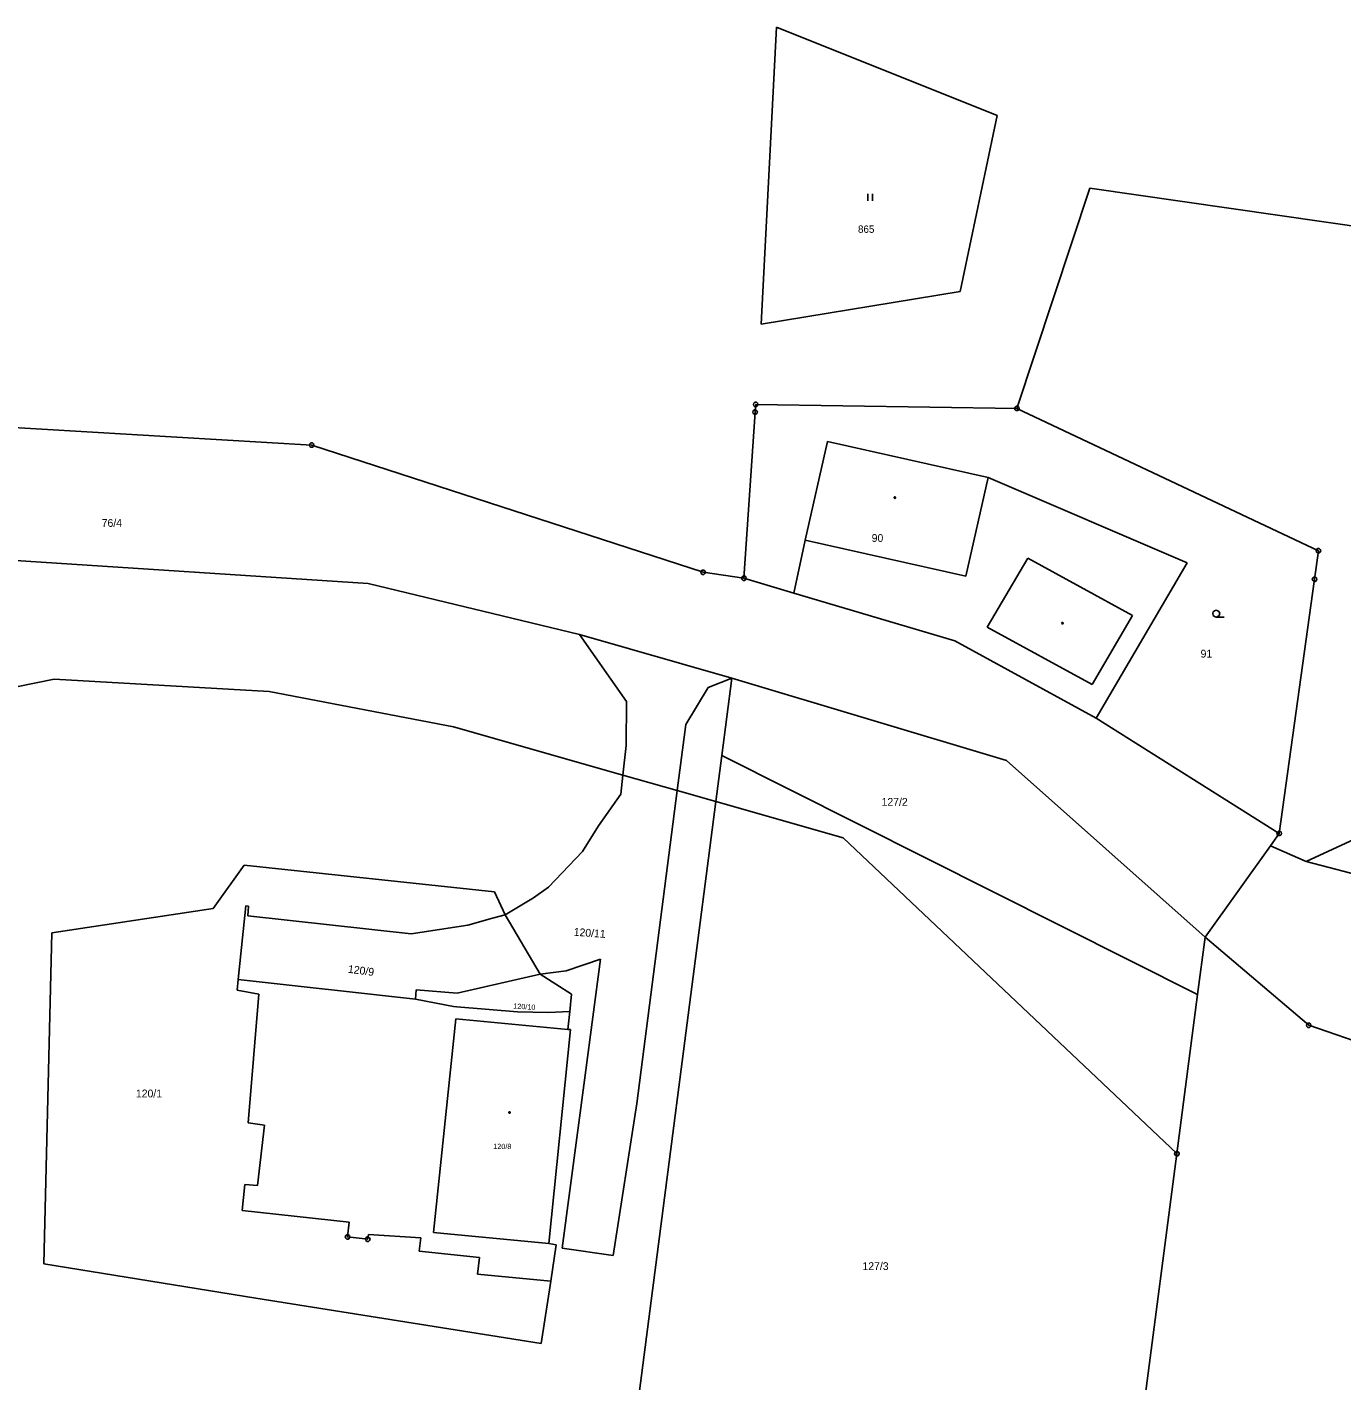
# Model space of a CAD drawing. Extents: x -871430 to -870620, y -1010094 to -1009649.
# Drawn here: x -870749.2 to -870677.7, y -1009821.3 to -1009747.7 of the extents above; entities that cross this region are included whole.
import ezdxf

# ---------------------------------------------------------------- set-up
doc = ezdxf.new("R2010")
doc.units = 0
for name, color, linetype in [('Vrstva 1', 7, 'Continuous'), ('Vrstva 2', 7, 'Continuous'), ('Vrstva 3', 7, 'Continuous'), ('Vrstva 4', 7, 'Continuous'), ('Vrstva 5', 7, 'Continuous'), ('Vrstva 8', 7, 'Continuous')]:
    doc.layers.add(name, color=color, linetype=linetype)

msp = doc.modelspace()

# ---------------------------------------------------------------- linework, layer by layer
at = {"layer": 'Vrstva 1'}
for p, q in [((-870708.42, -1009747.66), (-870709.26, -1009763.81)), ((-870696.42, -1009752.46), (-870708.42, -1009747.66)), ((-870698.43, -1009762.04), (-870696.42, -1009752.46)), ((-870695.35, -1009768.4), (-870691.39, -1009756.43)), ((-870691.39, -1009756.43), (-870620.429, -1009766.605)), ((-870709.26, -1009763.81), (-870698.43, -1009762.04)), ((-870709.59, -1009768.6), (-870709.56, -1009768.18)), ((-870695.35, -1009768.4), (-870709.56, -1009768.18)), ((-870678.95, -1009776.14), (-870695.35, -1009768.4)), ((-870710.2, -1009777.63), (-870709.59, -1009768.6)), ((-870733.71, -1009770.39), (-870751.26, -1009769.35)), ((-870712.42, -1009777.31), (-870733.71, -1009770.39)), ((-870706.87, -1009775.56), (-870705.66, -1009770.19)), ((-870705.66, -1009770.19), (-870696.91, -1009772.16)), ((-870686.09, -1009776.8), (-870696.91, -1009772.16)), ((-870706.87, -1009775.56), (-870707.48, -1009778.44)), ((-870679.16, -1009777.69), (-870678.95, -1009776.14)), ((-870750.1, -1009776.66), (-870730.64, -1009777.93)), ((-870691.04, -1009785.25), (-870686.09, -1009776.8)), ((-870730.64, -1009777.93), (-870719.14, -1009780.69)), ((-870710.2, -1009777.63), (-870712.42, -1009777.31)), ((-870707.48, -1009778.44), (-870710.2, -1009777.63)), ((-870681.08, -1009791.51), (-870679.16, -1009777.69)), ((-870698.72, -1009781.04), (-870707.48, -1009778.44)), ((-870716.59, -1009784.34), (-870719.14, -1009780.69)), ((-870719.14, -1009780.69), (-870710.86, -1009783.07)), ((-870698.72, -1009781.04), (-870691.04, -1009785.25)), ((-870712.14, -1009783.57), (-870710.86, -1009783.07)), ((-870710.86, -1009783.07), (-870711.4, -1009787.27)), ((-870710.86, -1009783.07), (-870695.92, -1009787.54)), ((-870713.36, -1009785.59), (-870712.14, -1009783.57)), ((-870716.61, -1009786.73), (-870716.59, -1009784.34)), ((-870681.08, -1009791.51), (-870691.04, -1009785.25)), ((-870713.83, -1009789.18), (-870713.36, -1009785.59)), ((-870716.78, -1009788.34), (-870716.61, -1009786.73)), ((-870711.4, -1009787.27), (-870711.73, -1009789.78)), ((-870711.4, -1009787.27), (-870685.52, -1009800.28)), ((-870695.92, -1009787.54), (-870685.11, -1009797.16)), ((-870716.89, -1009789.38), (-870716.78, -1009788.34)), ((-870718.1, -1009791.1), (-870716.89, -1009789.38)), ((-870711.73, -1009789.78), (-870716.33, -1009825.29)), ((-870716.03, -1009806.21), (-870713.83, -1009789.18)), ((-870718.98, -1009792.49), (-870718.1, -1009791.1)), ((-870681.56, -1009792.19), (-870681.08, -1009791.51)), ((-870679.62, -1009793.04), (-870676.52, -1009791.61)), ((-870720.82, -1009794.44), (-870718.98, -1009792.49)), ((-870685.11, -1009797.16), (-870681.56, -1009792.19)), ((-870679.62, -1009793.04), (-870681.56, -1009792.19)), ((-870739.07, -1009795.6), (-870737.38, -1009793.24)), ((-870737.38, -1009793.24), (-870723.77, -1009794.69)), ((-870663.26, -1009797.32), (-870679.62, -1009793.04)), ((-870723.77, -1009794.69), (-870723.19, -1009795.95)), ((-870721.65, -1009795.02), (-870720.82, -1009794.44)), ((-870747.84, -1009796.92), (-870739.07, -1009795.6)), ((-870737.7, -1009799.45), (-870737.29, -1009795.46)), ((-870737.29, -1009795.46), (-870737.14, -1009795.47)), ((-870737.14, -1009795.47), (-870737.18, -1009796)), ((-870723.19, -1009795.95), (-870721.65, -1009795.02)), ((-870737.18, -1009796), (-870728.29, -1009796.97)), ((-870725.21, -1009796.51), (-870723.88, -1009796.13)), ((-870723.88, -1009796.13), (-870723.19, -1009795.95)), ((-870723.19, -1009795.95), (-870721.28, -1009799.17)), ((-870748.28, -1009814.92), (-870747.84, -1009796.92)), ((-870728.29, -1009796.97), (-870725.21, -1009796.51)), ((-870685.11, -1009797.16), (-870685.52, -1009800.28)), ((-870685.11, -1009797.16), (-870679.48, -1009801.95)), ((-870719.86, -1009798.98), (-870718, -1009798.36)), ((-870718, -1009798.36), (-870718.83, -1009804.66)), ((-870725.8, -1009800.21), (-870721.28, -1009799.17)), ((-870721.28, -1009799.17), (-870719.86, -1009798.98)), ((-870721.28, -1009799.17), (-870719.58, -1009800.26)), ((-870737.76, -1009800.04), (-870737.7, -1009799.45)), ((-870736.59, -1009800.25), (-870737.76, -1009800.04)), ((-870728.07, -1009800.52), (-870737.7, -1009799.45)), ((-870728.03, -1009800.02), (-870728.07, -1009800.52)), ((-870728.03, -1009800.02), (-870725.8, -1009800.21)), ((-870736.59, -1009800.25), (-870737.16, -1009807.26)), ((-870728.07, -1009800.52), (-870726, -1009800.92)), ((-870719.58, -1009800.26), (-870719.67, -1009801.2)), ((-870685.52, -1009800.28), (-870686.65, -1009808.93)), ((-870726, -1009800.92), (-870725.82, -1009800.95)), ((-870725.82, -1009800.95), (-870722.52, -1009801.22)), ((-870722.52, -1009801.22), (-870720.84, -1009801.25)), ((-870720.84, -1009801.25), (-870719.67, -1009801.2)), ((-870719.67, -1009801.2), (-870719.77, -1009802.17)), ((-870720.81, -1009813.82), (-870719.64, -1009802.18)), ((-870719.64, -1009802.18), (-870719.77, -1009802.17)), ((-870679.48, -1009801.95), (-870669.09, -1009805.53)), ((-870718.83, -1009804.66), (-870720.08, -1009814.07)), ((-870717.32, -1009814.47), (-870716.03, -1009806.21)), ((-870737.16, -1009807.26), (-870736.28, -1009807.38)), ((-870736.28, -1009807.38), (-870736.66, -1009810.67)), ((-870689.91, -1009833.79), (-870686.65, -1009808.93)), ((-870737.34, -1009810.6), (-870737.49, -1009812.02)), ((-870736.66, -1009810.67), (-870737.34, -1009810.6)), ((-870737.49, -1009812.02), (-870731.67, -1009812.66)), ((-870731.67, -1009812.66), (-870731.76, -1009813.46)), ((-870730.66, -1009813.58), (-870730.62, -1009813.33)), ((-870730.62, -1009813.33), (-870727.77, -1009813.5)), ((-870731.76, -1009813.46), (-870730.66, -1009813.58)), ((-870727.77, -1009813.5), (-870727.86, -1009814.23)), ((-870720.81, -1009813.82), (-870720.42, -1009813.88)), ((-870720.7, -1009815.87), (-870720.42, -1009813.88)), ((-870720.08, -1009814.07), (-870717.32, -1009814.47)), ((-870727.86, -1009814.23), (-870724.59, -1009814.57)), ((-870724.59, -1009814.57), (-870724.69, -1009815.48)), ((-870736.74, -1009816.79), (-870748.28, -1009814.92)), ((-870724.69, -1009815.48), (-870720.7, -1009815.87)), ((-870720.7, -1009815.87), (-870721.23, -1009819.26)), ((-870721.23, -1009819.26), (-870736.74, -1009816.79))]:
    msp.add_line(p, q, dxfattribs=at)
at = {"layer": 'Vrstva 3'}
for p, q in [((-870703.455, -1009756.735), (-870703.455, -1009757.11)), ((-870703.205, -1009757.11), (-870703.205, -1009756.735))]:
    msp.add_line(p, q, dxfattribs=at)
msp.add_lwpolyline([(-870684.51, -1009779.75), (-870684.605, -1009779.725), (-870684.672, -1009779.655), (-870684.698, -1009779.562), (-870684.672, -1009779.47), (-870684.605, -1009779.4), (-870684.51, -1009779.375), (-870684.415, -1009779.4), (-870684.348, -1009779.47), (-870684.322, -1009779.562), (-870684.348, -1009779.655), (-870684.415, -1009779.725), (-870684.51, -1009779.75), (-870684.072, -1009779.75)], dxfattribs=at)
at = {"layer": 'Vrstva 4'}
for p, q in [((-870696.91, -1009772.16), (-870698.12, -1009777.53)), ((-870698.12, -1009777.53), (-870706.87, -1009775.56)), ((-870694.76, -1009776.54), (-870696.96, -1009780.29)), ((-870689.06, -1009779.66), (-870694.76, -1009776.54)), ((-870689.06, -1009779.66), (-870691.26, -1009783.41)), ((-870696.96, -1009780.29), (-870691.26, -1009783.41)), ((-870762.52, -1009786.18), (-870747.71, -1009783.12)), ((-870736.03, -1009783.8), (-870747.71, -1009783.12)), ((-870726, -1009785.71), (-870736.03, -1009783.8)), ((-870716.78, -1009788.34), (-870726, -1009785.71)), ((-870713.83, -1009789.18), (-870716.78, -1009788.34)), ((-870711.73, -1009789.78), (-870713.83, -1009789.18)), ((-870704.8, -1009791.76), (-870711.73, -1009789.78)), ((-870686.65, -1009808.93), (-870704.8, -1009791.76)), ((-870727.08, -1009813.21), (-870725.86, -1009801.6)), ((-870719.77, -1009802.17), (-870725.86, -1009801.6)), ((-870727.08, -1009813.21), (-870720.81, -1009813.82))]:
    msp.add_line(p, q, dxfattribs=at)
at = {"layer": 'Vrstva 5'}
for points in [[(-870701.99, -1009773.208), (-870701.965, -1009773.212), (-870701.952, -1009773.235), (-870701.948, -1009773.25), (-870701.952, -1009773.272), (-870701.972, -1009773.29), (-870701.99, -1009773.292), (-870702.012, -1009773.285), (-870702.028, -1009773.27), (-870702.032, -1009773.25), (-870702.028, -1009773.228), (-870702.008, -1009773.21), (-870701.99, -1009773.208)], [(-870692.848, -1009780.042), (-870692.825, -1009780.08), (-870692.848, -1009780.117), (-870692.892, -1009780.117), (-870692.915, -1009780.08), (-870692.892, -1009780.042), (-870692.848, -1009780.042)], [(-870722.95, -1009806.648), (-870722.925, -1009806.652), (-870722.912, -1009806.675), (-870722.908, -1009806.69), (-870722.912, -1009806.712), (-870722.932, -1009806.73), (-870722.95, -1009806.732), (-870722.972, -1009806.725), (-870722.987, -1009806.71), (-870722.992, -1009806.69), (-870722.987, -1009806.668), (-870722.967, -1009806.65), (-870722.95, -1009806.648)]]:
    msp.add_lwpolyline(points, dxfattribs=at)
at = {"layer": 'Vrstva 8'}
for p, q in [((-870709.572, -1009768.18), (-870709.548, -1009768.18)), ((-870695.362, -1009768.4), (-870695.338, -1009768.4)), ((-870709.602, -1009768.6), (-870709.578, -1009768.6)), ((-870733.722, -1009770.39), (-870733.698, -1009770.39)), ((-870678.962, -1009776.14), (-870678.938, -1009776.14)), ((-870712.432, -1009777.31), (-870712.408, -1009777.31)), ((-870710.212, -1009777.63), (-870710.188, -1009777.63)), ((-870679.172, -1009777.69), (-870679.148, -1009777.69)), ((-870681.092, -1009791.51), (-870681.068, -1009791.51)), ((-870679.492, -1009801.95), (-870679.468, -1009801.95)), ((-870686.662, -1009808.93), (-870686.638, -1009808.93)), ((-870731.772, -1009813.46), (-870731.748, -1009813.46)), ((-870730.672, -1009813.58), (-870730.648, -1009813.58))]:
    msp.add_line(p, q, dxfattribs=at)
for points in [[(-870709.523, -1009768.06), (-870709.46, -1009768.108), (-870709.435, -1009768.18), (-870709.46, -1009768.253), (-870709.523, -1009768.3), (-870709.598, -1009768.3), (-870709.66, -1009768.253), (-870709.685, -1009768.18), (-870709.66, -1009768.108), (-870709.598, -1009768.06), (-870709.523, -1009768.06)], [(-870695.312, -1009768.28), (-870695.25, -1009768.328), (-870695.225, -1009768.4), (-870695.25, -1009768.472), (-870695.312, -1009768.52), (-870695.388, -1009768.52), (-870695.45, -1009768.472), (-870695.475, -1009768.4), (-870695.45, -1009768.328), (-870695.388, -1009768.28), (-870695.312, -1009768.28)], [(-870709.552, -1009768.48), (-870709.49, -1009768.528), (-870709.465, -1009768.6), (-870709.49, -1009768.672), (-870709.552, -1009768.72), (-870709.628, -1009768.72), (-870709.69, -1009768.672), (-870709.715, -1009768.6), (-870709.69, -1009768.528), (-870709.628, -1009768.48), (-870709.552, -1009768.48)], [(-870733.672, -1009770.27), (-870733.61, -1009770.318), (-870733.585, -1009770.39), (-870733.61, -1009770.462), (-870733.672, -1009770.51), (-870733.747, -1009770.51), (-870733.81, -1009770.462), (-870733.835, -1009770.39), (-870733.81, -1009770.318), (-870733.747, -1009770.27), (-870733.672, -1009770.27)], [(-870678.912, -1009776.02), (-870678.85, -1009776.068), (-870678.825, -1009776.14), (-870678.85, -1009776.212), (-870678.912, -1009776.26), (-870678.987, -1009776.26), (-870679.05, -1009776.212), (-870679.075, -1009776.14), (-870679.05, -1009776.068), (-870678.987, -1009776.02), (-870678.912, -1009776.02)], [(-870712.383, -1009777.19), (-870712.32, -1009777.238), (-870712.295, -1009777.31), (-870712.32, -1009777.383), (-870712.383, -1009777.43), (-870712.458, -1009777.43), (-870712.52, -1009777.383), (-870712.545, -1009777.31), (-870712.52, -1009777.238), (-870712.458, -1009777.19), (-870712.383, -1009777.19)], [(-870710.162, -1009777.51), (-870710.1, -1009777.558), (-870710.075, -1009777.63), (-870710.1, -1009777.702), (-870710.162, -1009777.75), (-870710.237, -1009777.75), (-870710.3, -1009777.702), (-870710.325, -1009777.63), (-870710.3, -1009777.558), (-870710.237, -1009777.51), (-870710.162, -1009777.51)], [(-870679.122, -1009777.57), (-870679.06, -1009777.617), (-870679.035, -1009777.69), (-870679.06, -1009777.762), (-870679.122, -1009777.81), (-870679.198, -1009777.81), (-870679.26, -1009777.762), (-870679.285, -1009777.69), (-870679.26, -1009777.617), (-870679.198, -1009777.57), (-870679.122, -1009777.57)], [(-870681.042, -1009791.39), (-870680.98, -1009791.438), (-870680.955, -1009791.51), (-870680.98, -1009791.582), (-870681.042, -1009791.63), (-870681.117, -1009791.63), (-870681.18, -1009791.582), (-870681.205, -1009791.51), (-870681.18, -1009791.438), (-870681.117, -1009791.39), (-870681.042, -1009791.39)], [(-870679.442, -1009801.83), (-870679.38, -1009801.878), (-870679.355, -1009801.95), (-870679.38, -1009802.022), (-870679.442, -1009802.07), (-870679.518, -1009802.07), (-870679.58, -1009802.022), (-870679.605, -1009801.95), (-870679.58, -1009801.878), (-870679.518, -1009801.83), (-870679.442, -1009801.83)], [(-870686.612, -1009808.81), (-870686.55, -1009808.858), (-870686.525, -1009808.93), (-870686.55, -1009809.003), (-870686.612, -1009809.05), (-870686.688, -1009809.05), (-870686.75, -1009809.003), (-870686.775, -1009808.93), (-870686.75, -1009808.858), (-870686.688, -1009808.81), (-870686.612, -1009808.81)], [(-870731.722, -1009813.34), (-870731.66, -1009813.388), (-870731.635, -1009813.46), (-870731.66, -1009813.532), (-870731.722, -1009813.58), (-870731.798, -1009813.58), (-870731.86, -1009813.532), (-870731.885, -1009813.46), (-870731.86, -1009813.388), (-870731.798, -1009813.34), (-870731.722, -1009813.34)], [(-870730.622, -1009813.46), (-870730.56, -1009813.508), (-870730.535, -1009813.58), (-870730.56, -1009813.652), (-870730.622, -1009813.7), (-870730.698, -1009813.7), (-870730.76, -1009813.652), (-870730.785, -1009813.58), (-870730.76, -1009813.508), (-870730.698, -1009813.46), (-870730.622, -1009813.46)]]:
    msp.add_lwpolyline(points, dxfattribs=at)

# ---------------------------------------------------------------- texts
at = {"layer": 'Vrstva 2'}
for s, height, p in [('865', 0.4, (-870703.994, -1009758.85)), ('76/4', 0.425, (-870745.131, -1009774.84)), ('90', 0.425, (-870703.251, -1009775.66)), ('91', 0.425, (-870685.361, -1009781.95)), ('127/2', 0.425, (-870702.712, -1009790.01)), ('120/1', 0.425, (-870743.271, -1009805.87)), ('120/8', 0.285, (-870723.832, -1009808.68)), ('127/3', 0.425, (-870703.752, -1009815.26))]:
    msp.add_text(s, height=height, dxfattribs=at).set_placement(p)
for s, height, rotation, p in [('120/11', 0.425, 355.86409, (-870719.469, -1009797.074)), ('120/9', 0.425, 352.59823, (-870731.756, -1009799.087)), ('120/10', 0.285, 356.55164, (-870722.751, -1009801.04))]:
    msp.add_text(s, height=height, rotation=rotation, dxfattribs=at).set_placement(p)

doc.saveas('drawing.dxf')
